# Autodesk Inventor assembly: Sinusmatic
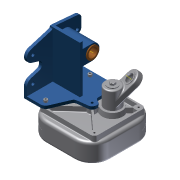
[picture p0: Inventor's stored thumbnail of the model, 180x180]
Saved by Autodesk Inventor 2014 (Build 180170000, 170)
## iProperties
Created: 2015-10
Part Number: Sinusmatic
Document SubType Name: Assembly
Designer: buchi
Author: buchi
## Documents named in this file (3)
- Y:\prof\0-année_2015_2016\1SI\TP\simulation inventor\barriere sinusmatic\Sinusmatic.iam
- Y:\prof\0-année_2015_2016\1SI\TP\simulation inventor\barriere sinusmatic\ens-carter.iam
- Y:\prof\0-année_2015_2016\1SI\TP\simulation inventor\barriere sinusmatic\ens-plateau.iam
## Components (2 placed, 2 different names)
1. ens-carter:1 [sub-assembly] — Rotation:1
2. ens-plateau:1 [sub-assembly] — Rotation:1
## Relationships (1: RevoluteJoint 1)
- Rotation:1 [RevoluteJoint]: ens-carter:1 ↔ ens-plateau:1
